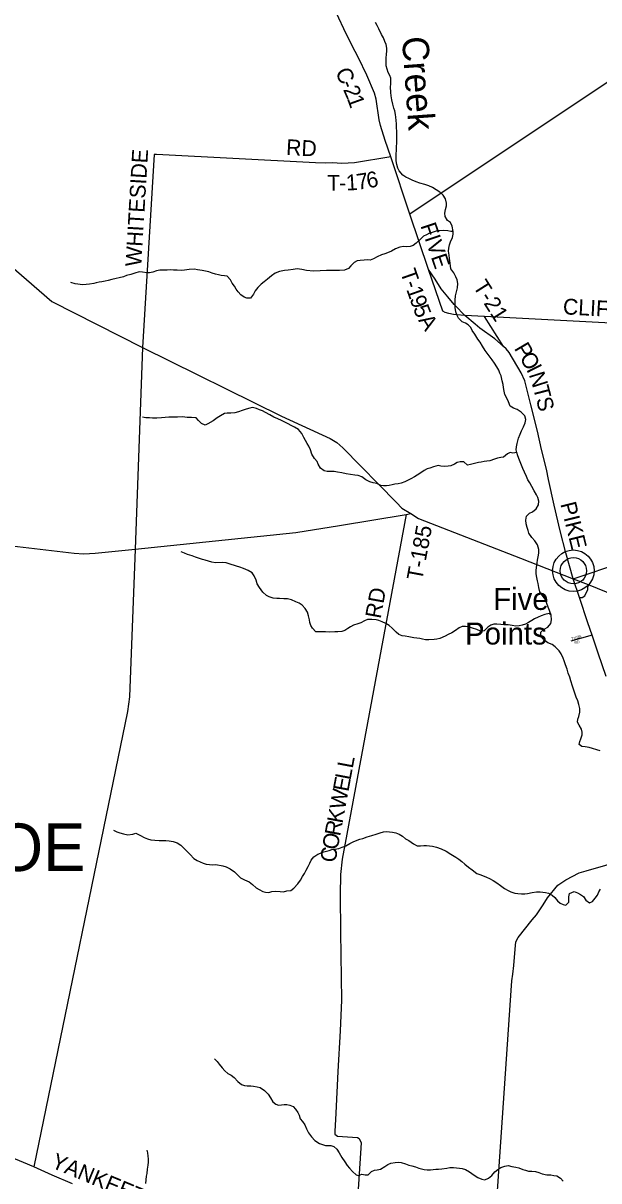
# Model space of a CAD drawing. Extents: x 1643459 to 2064572, y 425441 to 780708.
# Drawn here: x 1766596 to 1777506, y 599024 to 620966 of the extents above; entities that cross this region are included whole.
import ezdxf

# ---------------------------------------------------------------- set-up
doc = ezdxf.new("R2010")
doc.units = 0
for name, color, linetype in [('GE_P_Alignment_100_Curve_Data', 7, 'Continuous'), ('GM_X_Adjacent_County_Text', 7, 'Continuous'), ('GM_X_County', 7, 'Continuous'), ('GM_X_Interchange_Ramps', 7, 'Continuous'), ('GM_X_Major_River', 7, 'Continuous'), ('GM_X_Major_River_Text', 7, 'Continuous'), ('GM_X_Minor_Lake', 7, 'Continuous'), ('GM_X_Rail_Line', 7, 'Continuous'), ('GM_X_Section_Text', 7, 'Continuous'), ('GM_X_Township', 7, 'Continuous'), ('GM_X_Township_ROW', 7, 'Continuous'), ('GM_X_US_Route', 7, 'Continuous'), ('RD_X_Text', 7, 'Continuous')]:
    doc.layers.add(name, color=color, linetype=linetype)

msp = doc.modelspace()

# ---------------------------------------------------------------- linework, layer by layer
at = {"layer": 'GE_P_Alignment_100_Curve_Data'}
for radius in [393, 249]:
    msp.add_circle((1777024, 610588), radius, dxfattribs=at)
at = {"layer": 'GM_X_County'}
for points in [[(1777140, 610080), (1777189, 610081), (1777242, 610112), (1777300, 610235), (1777301, 610324)], [(1777379, 609364), (1776976, 609250)]]:
    msp.add_lwpolyline(points, dxfattribs=at)
at = {"layer": 'GM_X_Major_River_Text'}
for points in [[(1781934, 622690), (1781837, 622626), (1781604, 622471), (1781160, 622171), (1779067, 620775), (1773925, 617348)], [(1769122, 618477), (1769076, 618479), (1768855, 614819)], [(1773562, 618432), (1772874, 618320), (1772634, 618309), (1772456, 618320), (1772317, 618310), (1772135, 618317), (1769124, 618476), (1769122, 618477)], [(1774969, 615428), (1774811, 615440), (1774751, 615445), (1774665, 615465), (1774591, 615480), (1774551, 615506), (1774276, 616296)], [(1782541, 615030), (1775340, 615408), (1774969, 615428)], [(1775701, 614839), (1775340, 615408)], [(1768855, 614819), (1768722, 610994)], [(1761616, 611534), (1763461, 611453), (1763756, 611418), (1764584, 611273), (1765836, 611125), (1767560, 610918), (1767748, 610905), (1767958, 610922), (1768722, 610994)], [(1768722, 610994), (1771765, 611310), (1772594, 611445), (1773856, 611655), (1773945, 611670)], [(1773856, 611655), (1772731, 605592), (1772642, 605119), (1772612, 604830), (1772604, 604443), (1772611, 603737), (1772628, 602451), (1772607, 601870), (1772561, 601097), (1772524, 600307), (1772502, 599962), (1772506, 599910), (1772556, 599872), (1772935, 599844), (1772967, 599828), (1773000, 599743), (1772804, 596711)], [(1768722, 610994), (1768609, 608200), (1768572, 607919), (1766799, 599288)], [(1775613, 595594), (1775628, 595745), (1775605, 595867), (1775470, 596279), (1775455, 596409), (1775456, 596891), (1775858, 602814), (1775878, 602941), (1775893, 603105), (1775919, 603416), (1775936, 603556), (1775980, 603638), (1776241, 603970), (1776327, 604068), (1776452, 604256), (1776531, 604386), (1776729, 604627), (1776882, 604731), (1777131, 604864), (1777265, 604900), (1779128, 605436)]]:
    msp.add_lwpolyline(points, dxfattribs=at)
at = {"layer": 'GM_X_Minor_Lake'}
for points in [[(1777021, 610437), (1777021, 610437), (1776879, 610930), (1776773, 611342), (1776659, 611830), (1776551, 612316), (1776514, 612511), (1776422, 612888), (1776344, 613232), (1776220, 613734), (1776155, 613985), (1776128, 614088), (1776102, 614190), (1776031, 614337), (1775805, 614721), (1775751, 614796), (1775701, 614839), (1775538, 614982), (1775252, 615184), (1775164, 615258), (1774969, 615428), (1774781, 615613), (1774762, 615632), (1774642, 615779), (1774519, 615928), (1774402, 616111), (1774276, 616296), (1773925, 617348), (1773562, 618432), (1773458, 618742), (1773367, 619025), (1773342, 619136), (1773288, 619523), (1773256, 619640), (1773110, 619980), (1772953, 620309), (1772828, 620551), (1772673, 620857), (1772481, 621261)], [(1777642, 608585), (1777494, 609027), (1777379, 609364), (1777300, 609598), (1777140, 610080), (1777021, 610437)], [(1767530, 598970), (1767148, 599134), (1766799, 599288), (1765393, 599875), (1764985, 600041), (1764875, 600092)]]:
    msp.add_lwpolyline(points, dxfattribs=at)
at = {"layer": 'GM_X_Rail_Line'}
msp.add_line((1777024, 610588), (1777024, 610588), dxfattribs=at)
at = {"layer": 'GM_X_US_Route'}
for points in [[(1774747, 617017), (1774726, 617119), (1774692, 617190), (1774638, 617228), (1774591, 617301), (1774585, 617363), (1774600, 617433), (1774622, 617506), (1774618, 617556), (1774599, 617634), (1774555, 617703), (1774492, 617761), (1774426, 617808), (1774354, 617850), (1774286, 617881), (1774206, 617907), (1774116, 617934), (1774042, 617959), (1773970, 617989), (1773904, 618022), (1773850, 618050), (1773792, 618086), (1773725, 618165), (1773699, 618217), (1773679, 618286), (1773666, 618354), (1773664, 618412), (1773663, 618481), (1773669, 618557), (1773674, 618607), (1773676, 618708), (1773677, 618848), (1773680, 618918), (1773674, 618979), (1773671, 619055), (1773667, 619121), (1773660, 619182), (1773652, 619234), (1773638, 619302), (1773623, 619356), (1773603, 619429), (1773584, 619513), (1773570, 619586), (1773563, 619654), (1773557, 619758), (1773564, 619809), (1773566, 619863), (1773561, 619921), (1773545, 619975), (1773515, 620032), (1773492, 620094), (1773476, 620156), (1773475, 620235), (1773475, 620303), (1773482, 620381), (1773486, 620433), (1773488, 620492), (1773475, 620560), (1773453, 620620), (1773424, 620685), (1773390, 620751), (1773339, 620856), (1773305, 620920), (1773275, 620979)], [(1774747, 617017), (1774703, 617019), (1774647, 617029), (1774555, 617034), (1774494, 617032), (1774444, 617029), (1774346, 616999), (1774296, 616983), (1774241, 616955), (1774185, 616930), (1774126, 616874), (1774046, 616796), (1773985, 616754), (1773929, 616730), (1773867, 616728), (1773803, 616731), (1773732, 616723), (1773652, 616689), (1773575, 616646), (1773503, 616610), (1773453, 616594), (1773388, 616574), (1773308, 616537), (1773233, 616497), (1773171, 616477), (1773113, 616478), (1773057, 616476), (1772981, 616468), (1772926, 616460), (1772872, 616429), (1772807, 616367), (1772765, 616313), (1772689, 616285), (1772590, 616280), (1772478, 616278), (1772344, 616275), (1772223, 616270), (1772101, 616264), (1771965, 616277), (1771879, 616294), (1771790, 616310), (1771714, 616298), (1771618, 616287), (1771548, 616279), (1771453, 616260), (1771375, 616228), (1771304, 616176), (1771228, 616114), (1771165, 616064), (1771109, 616017), (1771044, 615957), (1770995, 615893), (1770961, 615831), (1770904, 615755), (1770838, 615755), (1770786, 615773), (1770720, 615814), (1770669, 615872), (1770633, 615923), (1770601, 615981), (1770557, 616038), (1770526, 616104), (1770460, 616169), (1770410, 616175), (1770350, 616181), (1770300, 616198), (1770244, 616206), (1770178, 616227), (1770118, 616255), (1770054, 616265), (1769990, 616278), (1769902, 616290), (1769841, 616301), (1769741, 616297), (1769655, 616282), (1769591, 616280), (1769518, 616282), (1769448, 616287), (1769388, 616289), (1769324, 616287), (1769256, 616282), (1769188, 616282), (1769121, 616272), (1769051, 616245), (1768989, 616233), (1768937, 616231), (1768855, 616244), (1768794, 616250), (1768712, 616228), (1768638, 616205), (1768557, 616183), (1768501, 616161), (1768276, 616106), (1768210, 616091), (1768152, 616077), (1768087, 616065), (1768035, 616057), (1767983, 616046), (1767933, 616032), (1767854, 616022), (1767792, 616015)], [(1776369, 610273), (1776356, 610343), (1776344, 610399), (1776327, 610488), (1776317, 610538), (1776320, 610594), (1776324, 610652), (1776337, 610737), (1776343, 610789), (1776355, 610853), (1776370, 610919), (1776372, 610992), (1776343, 611080), (1776291, 611153), (1776234, 611219), (1776182, 611302), (1776164, 611352), (1776147, 611404), (1776131, 611479), (1776124, 611547), (1776136, 611623), (1776195, 611677), (1776247, 611707), (1776318, 611759), (1776360, 611837), (1776369, 611907), (1776349, 611976), (1776324, 612026), (1776280, 612100), (1776235, 612185), (1776197, 612256), (1776161, 612312), (1776132, 612376), (1776098, 612457), (1776063, 612527), (1776027, 612620), (1776004, 612686), (1775972, 612763), (1775952, 612827), (1775941, 612877), (1775945, 612934), (1775958, 612998), (1775986, 613098), (1776017, 613178), (1776042, 613240), (1776078, 613312), (1776113, 613393), (1776121, 613451), (1776102, 613525), (1776036, 613596), (1775960, 613642), (1775890, 613671), (1775826, 613709), (1775793, 613792), (1775753, 613871), (1775726, 613931), (1775712, 613993), (1775700, 614058), (1775693, 614116), (1775677, 614184), (1775654, 614281), (1775632, 614331), (1775609, 614387), (1775573, 614452), (1775527, 614522), (1775482, 614583), (1775410, 614686), (1775349, 614760), (1775303, 614847), (1775255, 614920), (1775212, 614976), (1775154, 615073), (1775105, 615143), (1775083, 615200), (1775029, 615250), (1774977, 615280), (1774915, 615303), (1774844, 615376), (1774820, 615426), (1774796, 615492), (1774785, 615575), (1774783, 615641), (1774784, 615713), (1774790, 615800), (1774807, 615876), (1774826, 615948), (1774834, 616032), (1774821, 616101), (1774793, 616161), (1774755, 616236), (1774704, 616312), (1774687, 616415), (1774679, 616503), (1774670, 616571), (1774656, 616646), (1774665, 616704), (1774679, 616764), (1774695, 616820), (1774732, 616906), (1774743, 616965), (1774747, 617017)], [(1767792, 616015), (1767718, 616005), (1767630, 616017), (1767580, 616028), (1767500, 616050)], [(1769617, 613502), (1769523, 613499), (1769354, 613496), (1769286, 613494), (1769216, 613486), (1769132, 613479), (1769047, 613481), (1768991, 613488), (1768923, 613488), (1768861, 613498)], [(1775952, 612827), (1775878, 612816), (1775824, 612826), (1775772, 612802), (1775701, 612738), (1775647, 612732), (1775587, 612721), (1775526, 612701), (1775440, 612673), (1775384, 612664), (1775334, 612658), (1775277, 612648), (1775223, 612638), (1775147, 612621), (1775073, 612603), (1775014, 612591), (1774949, 612652), (1774878, 612654), (1774820, 612641), (1774768, 612605), (1774703, 612575), (1774651, 612569), (1774585, 612566), (1774511, 612570), (1774459, 612580), (1774372, 612557), (1774304, 612533), (1774254, 612517), (1774193, 612485), (1774115, 612432), (1774063, 612398), (1774012, 612370), (1773944, 612332), (1773883, 612298), (1773829, 612272), (1773761, 612249), (1773700, 612233), (1773642, 612227), (1773590, 612218), (1773532, 612204), (1773482, 612196), (1773427, 612194), (1773373, 612205), (1773297, 612241), (1773229, 612256), (1773165, 612272), (1773093, 612313), (1773016, 612365), (1772948, 612390), (1772882, 612400), (1772797, 612411), (1772715, 612427), (1772635, 612444), (1772555, 612458), (1772489, 612471), (1772357, 612471), (1772301, 612478), (1772233, 612530), (1772189, 612607), (1772168, 612659), (1772120, 612718), (1772068, 612798), (1772041, 612879), (1772009, 612947), (1771977, 612999), (1771944, 613056), (1771914, 613114), (1771875, 613187), (1771815, 613263), (1771741, 613310), (1771675, 613340), (1771617, 613369), (1771565, 613399), (1771491, 613434), (1771421, 613466), (1771345, 613499), (1771270, 613542), (1771186, 613584), (1771132, 613617), (1771076, 613639), (1771020, 613663), (1770944, 613682), (1770893, 613668), (1770821, 613652), (1770745, 613627), (1770680, 613599), (1770606, 613581), (1770530, 613576), (1770464, 613574), (1770412, 613568), (1770335, 613526), (1770271, 613483), (1770200, 613427), (1770093, 613371), (1770043, 613347), (1769973, 613376), (1769919, 613436), (1769872, 613487), (1769787, 613489), (1769707, 613494), (1769617, 613502)], [(1770241, 610738), (1770175, 610748), (1770109, 610768), (1770045, 610789), (1769995, 610801), (1769937, 610818), (1769865, 610846), (1769797, 610869), (1769713, 610895), (1769653, 610920), (1769593, 610948)], [(1776600, 609743), (1776562, 609780), (1776484, 609760), (1776412, 609732), (1776359, 609709), (1776287, 609673), (1776237, 609647), (1776176, 609609), (1776114, 609575), (1776054, 609558), (1775993, 609542), (1775933, 609536), (1775865, 609547), (1775787, 609561), (1775703, 609564), (1775647, 609570), (1775574, 609574), (1775518, 609575), (1775460, 609553), (1775404, 609517), (1775333, 609447), (1775261, 609445), (1775195, 609476), (1775113, 609502), (1775035, 609525), (1774979, 609533), (1774914, 609528), (1774862, 609504), (1774788, 609454), (1774719, 609412), (1774653, 609382), (1774596, 609345), (1774492, 609301), (1774438, 609291), (1774387, 609286), (1774287, 609280), (1774221, 609278), (1774163, 609291), (1774113, 609305), (1774057, 609311), (1773997, 609318), (1773906, 609332), (1773836, 609347), (1773776, 609351), (1773716, 609382), (1773664, 609422), (1773591, 609501), (1773531, 609547), (1773467, 609590), (1773403, 609622), (1773339, 609645), (1773285, 609655), (1773203, 609665), (1773125, 609662), (1773062, 609636), (1772996, 609598), (1772940, 609583), (1772859, 609559), (1772799, 609527), (1772747, 609491), (1772692, 609457), (1772634, 609434), (1772558, 609428), (1772500, 609428), (1772407, 609425), (1772329, 609427), (1772267, 609430), (1772211, 609430), (1772141, 609428), (1772077, 609497), (1772047, 609547), (1772030, 609604), (1772020, 609658), (1772006, 609734), (1771985, 609805), (1771939, 609869), (1771882, 609936), (1771824, 609974), (1771764, 610001), (1771680, 610033), (1771608, 610054), (1771538, 610058), (1771453, 610062), (1771403, 610063), (1771335, 610067), (1771257, 610092), (1771205, 610120), (1771137, 610183), (1771076, 610271), (1771034, 610340), (1771015, 610408), (1770977, 610493), (1770937, 610549), (1770858, 610592), (1770774, 610628), (1770700, 610655), (1770640, 610673), (1770502, 610720), (1770442, 610735), (1770365, 610741), (1770241, 610738)], [(1777534, 607174), (1777470, 607195), (1777386, 607219), (1777320, 607238), (1777246, 607252), (1777184, 607256), (1777132, 607293), (1777145, 607349), (1777163, 607401), (1777192, 607477), (1777192, 607531), (1777178, 607584), (1777133, 607660), (1777103, 607719), (1777110, 607775), (1777128, 607825), (1777143, 607905), (1777143, 607975), (1777128, 608052), (1777108, 608124), (1777076, 608193), (1777055, 608251), (1777039, 608307), (1777008, 608402), (1776976, 608504), (1776955, 608573), (1776923, 608645), (1776904, 608724), (1776876, 608806), (1776849, 608879), (1776827, 608933), (1776792, 609013), (1776754, 609070), (1776680, 609147), (1776620, 609189), (1776540, 609224), (1776487, 609260), (1776431, 609309), (1776409, 609361), (1776405, 609421), (1776470, 609483), (1776538, 609517), (1776595, 609587), (1776612, 609657), (1776600, 609743), (1776573, 609836), (1776545, 609900), (1776522, 609967), (1776498, 610043), (1776430, 610124), (1776385, 610186), (1776369, 610273)], [(1768308, 605668), (1768370, 605642), (1768428, 605621), (1768498, 605601), (1768580, 605584), (1768673, 605594), (1768729, 605612), (1768821, 605571), (1768891, 605529), (1768955, 605504), (1769015, 605490), (1769091, 605479), (1769175, 605475), (1769241, 605472), (1769299, 605476), (1769365, 605470), (1769438, 605457), (1769516, 605433), (1769585, 605384), (1769659, 605312), (1769761, 605209), (1769828, 605136), (1769892, 605094), (1770006, 605043), (1770066, 605028), (1770128, 605020), (1770180, 605016), (1770250, 605017), (1770379, 604992), (1770445, 604976), (1770517, 604936), (1770602, 604883), (1770662, 604820), (1770716, 604766), (1770792, 604727), (1770878, 604691), (1770944, 604638), (1771013, 604576), (1771067, 604545), (1771139, 604509), (1771191, 604494), (1771251, 604490), (1771310, 604510), (1771384, 604513), (1771466, 604505), (1771528, 604504), (1771596, 604520), (1771667, 604530), (1771723, 604570), (1771804, 604654), (1771850, 604720), (1771893, 604794), (1771926, 604852), (1771958, 604912), (1771995, 604980), (1772031, 605046), (1772052, 605100), (1772104, 605164), (1772183, 605218), (1772297, 605259), (1772394, 605287), (1772446, 605305), (1772506, 605312), (1772579, 605326), (1772643, 605348), (1772709, 605375), (1772784, 605415), (1772866, 605455), (1772975, 605498), (1773033, 605512), (1773118, 605544), (1773202, 605572), (1773286, 605597), (1773363, 605621), (1773425, 605637), (1773485, 605644), (1773541, 605642), (1773593, 605632), (1773657, 605619), (1773719, 605597), (1773787, 605560), (1773843, 605508), (1773905, 605475), (1773991, 605409), (1774063, 605376), (1774129, 605372), (1774187, 605379), (1774241, 605377), (1774352, 605369), (1774428, 605348), (1774516, 605315), (1774611, 605271), (1774703, 605214), (1774793, 605157), (1774855, 605123), (1774909, 605074), (1774969, 605026), (1775038, 604967), (1775108, 604919), (1775192, 604850), (1775270, 604823)], [(1775270, 604823), (1775376, 604781), (1775434, 604752), (1775504, 604716), (1775570, 604673), (1775642, 604619), (1775719, 604566), (1775785, 604530), (1775839, 604503), (1775917, 604479), (1775973, 604470), (1776043, 604466), (1776102, 604464), (1776152, 604469), (1776244, 604491), (1776326, 604502), (1776393, 604504), (1776495, 604492), (1776549, 604475), (1776619, 604441), (1776673, 604394), (1776720, 604332), (1776772, 604285), (1776828, 604261), (1776878, 604250), (1776935, 604304), (1776935, 604359), (1776939, 604409), (1776952, 604471), (1777036, 604507), (1777104, 604486), (1777160, 604450), (1777218, 604413), (1777258, 604347), (1777326, 604296), (1777384, 604320), (1777436, 604382), (1777481, 604440), (1777505, 604504), (1777536, 604554)], [(1770220, 601335), (1770272, 601289), (1770308, 601237), (1770369, 601166), (1770419, 601112), (1770473, 601057), (1770537, 601025), (1770597, 600982), (1770664, 600905), (1770736, 600853), (1770790, 600834), (1770844, 600828), (1770910, 600822), (1770961, 600816), (1771033, 600807), (1771089, 600791), (1771168, 600734), (1771240, 600665), (1771282, 600595), (1771327, 600522), (1771383, 600476), (1771435, 600458), (1771493, 600467), (1771544, 600473), (1771596, 600469), (1771650, 600456), (1771712, 600434), (1771758, 600384), (1771803, 600319), (1771827, 600269), (1771844, 600198), (1771888, 600146), (1771936, 600083), (1771965, 600013), (1772005, 599931), (1772059, 599856), (1772126, 599789), (1772212, 599735), (1772266, 599712), (1772328, 599696), (1772378, 599692), (1772430, 599691), (1772484, 599673), (1772540, 599624), (1772588, 599558), (1772637, 599467), (1772693, 599387), (1772738, 599318), (1772782, 599262), (1772836, 599199), (1772904, 599137), (1772954, 599128), (1773014, 599150), (1773078, 599140), (1773136, 599139), (1773199, 599199), (1773257, 599229), (1773307, 599235), (1773370, 599243), (1773448, 599298), (1773505, 599332), (1773567, 599360), (1773649, 599374), (1773705, 599377), (1773763, 599369), (1773844, 599344), (1773908, 599324), (1773964, 599306), (1774032, 599289), (1774092, 599267), (1774194, 599236), (1774254, 599232), (1774314, 599233), (1774414, 599243), (1774466, 599247), (1774529, 599254), (1774627, 599266), (1774681, 599274), (1774749, 599275), (1774810, 599271), (1774866, 599264), (1774918, 599256), (1774978, 599240), (1775056, 599195), (1775145, 599130), (1775211, 599090), (1775287, 599053), (1775343, 599043), (1775416, 599073), (1775478, 599125), (1775533, 599193), (1775593, 599240), (1775648, 599278), (1775722, 599304), (1775788, 599312), (1775856, 599297), (1775935, 599285), (1775987, 599270), (1776065, 599238), (1776119, 599228), (1776175, 599207)], [(1768943, 599608), (1768955, 599558), (1768962, 599491), (1768966, 599439), (1768963, 599375), (1768959, 599321), (1768948, 599248), (1768938, 599166), (1768929, 599112), (1768921, 599044), (1768912, 598974)], [(1776175, 599207), (1776235, 599209), (1776307, 599202), (1776367, 599182), (1776435, 599154), (1776521, 599139), (1776597, 599139), (1776655, 599128), (1776711, 599118), (1776781, 599075), (1776833, 599015)]]:
    msp.add_lwpolyline(points, dxfattribs=at)
at = {"layer": 'RD_X_Text'}
for points in [[(1757232, 625314), (1758391, 625211), (1758421, 625192), (1758715, 624823), (1759231, 624246), (1760568, 622684), (1763244, 619552), (1765022, 617523), (1767140, 615688), (1768855, 614819), (1771492, 613520), (1772414, 613091), (1772539, 613016), (1772653, 612916), (1773673, 611884), (1773774, 611775), (1773945, 611670), (1774091, 611580), (1776024, 610826)], [(1777021, 610437), (1781723, 612013), (1783705, 613106), (1784037, 613289), (1785470, 614182), (1788508, 616074), (1793844, 617891)], [(1776024, 610826), (1777021, 610437), (1777301, 610324), (1780885, 608867), (1781769, 608388), (1782581, 608065), (1783790, 607688), (1784085, 607562), (1784931, 607037), (1785328, 606791), (1785462, 606705), (1786867, 606458), (1787694, 606306), (1789055, 605851), (1790576, 605545), (1791756, 605204)]]:
    msp.add_lwpolyline(points, dxfattribs=at)

# ---------------------------------------------------------------- texts
at = {"layer": 'GM_X_Adjacent_County_Text'}
msp.add_text('MONROE', height=900, rotation=0, dxfattribs=at).set_placement((1762361, 604897))
at = {"layer": 'GM_X_Interchange_Ramps'}
msp.add_text('Creek', height=500.1, rotation=274.1143, dxfattribs=at).set_placement((1773773, 620699))
at = {"layer": 'GM_X_Major_River'}
for s, rotation, p in [('RD', 357.0407, (1771574, 618468)), ('WHITESIDE', 86.589, (1768833, 616346)), ('7', 8.7539, (1772937, 617806)), ('6', 9.9123, (1773127, 617835)), ('T', 0.1157, (1772356, 617790)), ('-', 0.9582, (1772585, 617790)), ('1', 3.0631, (1772721, 617793)), ('T', 289.3396, (1773739, 616250)), ('T-21', 302.4137, (1775112, 615979)), ('1', 289.3985, (1773854, 615922)), ('-', 289.3412, (1773813, 616038)), ('9', 289.8031, (1773916, 615745)), ('CLIFTON', 356.9102, (1776820, 615449)), ('5', 291.1436, (1773981, 615564)), ('A', 302.4059, (1774077, 615335)), ('T-185', 79.5186, (1774157, 610388)), ('RD', 79.5624, (1773371, 609668)), ('L', 79.4188, (1772841, 606830)), ('L', 79.4213, (1772800, 606609)), ('E', 79.4188, (1772759, 606388)), ('W', 79.4196, (1772695, 606047)), ('K', 79.4195, (1772647, 605787)), ('R', 79.4192, (1772601, 605545)), ('O', 79.4902, (1772553, 605285)), ('C', 81.898, (1772519, 605045))]:
    msp.add_text(s, height=300, rotation=rotation, dxfattribs=at).set_placement(p)
at = {"layer": 'GM_X_Section_Text'}
for s, rotation, p in [('C', 294.0822, (1772506, 620045)), ('2', 293.7107, (1772656, 619708)), ('-', 294.0124, (1772606, 619820)), ('1', 289.88, (1772729, 619543)), ('FIVE', 288.6313, (1774122, 617129)), ('P', 300.4097, (1775893, 614803)), ('O', 300.011, (1775995, 614629)), ('I', 297.1132, (1776126, 614404)), ('N', 287.7611, (1776177, 614306)), ('T', 284.5955, (1776256, 614059)), ('S', 284.5191, (1776313, 613842)), ('PIKE', 283.887, (1776774, 611855)), ('YANKEETOWN', 337.4593, (1767108, 599284))]:
    msp.add_text(s, height=300, rotation=rotation, dxfattribs=at).set_placement(p)
at = {"layer": 'GM_X_Township'}
for s, rotation, p in [('T1038', 15.9429, (1776991, 609268)), ('RD', 15.526, (1777049, 609195))]:
    msp.add_text(s, height=50, rotation=rotation, dxfattribs=at).set_placement(p)
at = {"layer": 'GM_X_Township_ROW'}
for s, p in [('Five', (1775502, 609845)), ('Points', (1774970, 609189))]:
    msp.add_text(s, height=417, rotation=0, dxfattribs=at).set_placement(p)

doc.saveas('drawing.dxf')
